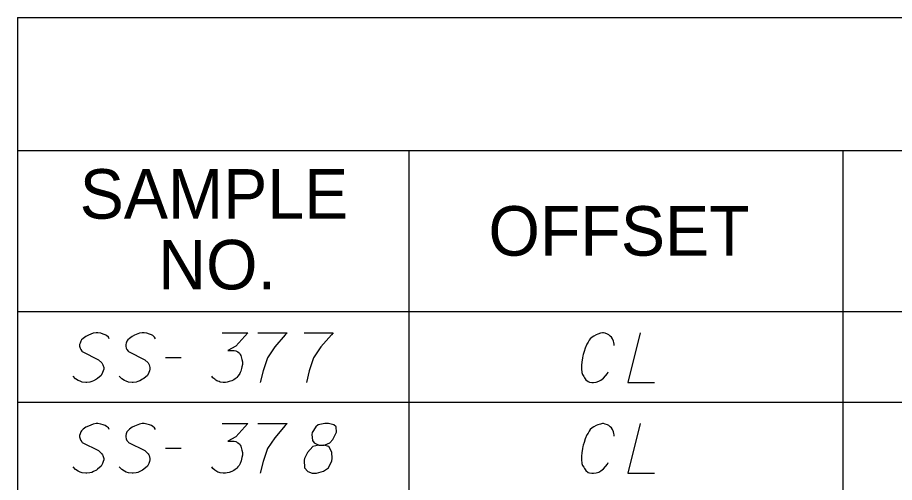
# Model space of a CAD drawing. Extents: x 2074207 to 2076812, y 516372 to 523312.
# Drawn here: x 2076260.6 to 2076345.6, y 517347 to 517392.1 of the extents above; entities that cross this region are included whole.
import ezdxf

# ---------------------------------------------------------------- set-up
doc = ezdxf.new("R2010")
doc.units = 0
for name, color, linetype in [('Prop DirtTable_ Soil Test Results - Outline (Major)', 7, 'Continuous'), ('Prop DirtTable_ Soil Test Results - Outline (Minor)', 7, 'Continuous'), ('Prop DirtTable_ Soil Test Results - Tx (Header - Small)', 7, 'Continuous'), ('Prop DirtTable_ Soil Test Results - Tx (Sample Data)', 7, 'Continuous')]:
    doc.layers.add(name, color=color, linetype=linetype)

msp = doc.modelspace()

# ---------------------------------------------------------------- linework, layer by layer
at = {"layer": 'Prop DirtTable_ Soil Test Results - Outline (Major)'}
for p, q in [((2076260.609, 517392.071), (2076260.609, 517363.585)), ((2076260.609, 517392.071), (2076811.903, 517392.071)), ((2076260.609, 517363.585), (2076260.609, 517354.785)), ((2076260.609, 517363.585), (2076811.903, 517363.585)), ((2076260.609, 517363.585), (2076811.903, 517363.585)), ((2076260.609, 517354.785), (2076260.609, 517345.985))]:
    msp.add_line(p, q, dxfattribs=at)
at = {"layer": 'Prop DirtTable_ Soil Test Results - Outline (Minor)'}
for p, q in [((2076260.609, 517379.185), (2076811.903, 517379.185)), ((2076298.545, 517379.185), (2076298.545, 517354.785)), ((2076340.594, 517379.185), (2076340.594, 517354.785)), ((2076260.609, 517354.785), (2076811.903, 517354.785)), ((2076260.609, 517354.785), (2076811.903, 517354.785)), ((2076298.546, 517354.785), (2076298.546, 517345.985)), ((2076340.594, 517354.785), (2076340.594, 517345.985))]:
    msp.add_line(p, q, dxfattribs=at)
at = {"layer": 'Prop DirtTable_ Soil Test Results - Tx (Sample Data)'}
for points in [[(2076269.488, 517360.931), (2076269.417, 517361.082), (2076269.241, 517361.233), (2076269.1, 517361.309), (2076268.923, 517361.385), (2076268.677, 517361.46), (2076268.394, 517361.498), (2076268.218, 517361.498), (2076267.936, 517361.46), (2076267.477, 517361.271), (2076267.23, 517361.158), (2076266.983, 517360.969), (2076266.807, 517360.818), (2076266.736, 517360.704), (2076266.666, 517360.515), (2076266.631, 517360.364), (2076266.631, 517360.213), (2076266.666, 517360.024), (2076266.736, 517359.873), (2076266.842, 517359.722), (2076266.878, 517359.684), (2076268.465, 517358.89), (2076268.782, 517358.588), (2076268.853, 517358.474), (2076268.888, 517358.399), (2076268.959, 517358.134), (2076268.959, 517357.983), (2076268.923, 517357.832), (2076268.853, 517357.643), (2076268.712, 517357.378), (2076268.359, 517357.076), (2076268.253, 517357), (2076267.971, 517356.849), (2076267.795, 517356.774), (2076267.618, 517356.736), (2076267.336, 517356.698), (2076267.23, 517356.698), (2076266.878, 517356.736), (2076266.666, 517356.811), (2076266.489, 517356.887), (2076266.243, 517357.038), (2076265.996, 517357.303)], [(2076273.968, 517360.931), (2076273.897, 517361.082), (2076273.721, 517361.233), (2076273.58, 517361.309), (2076273.403, 517361.385), (2076273.157, 517361.46), (2076272.874, 517361.498), (2076272.698, 517361.498), (2076272.416, 517361.46), (2076271.957, 517361.271), (2076271.71, 517361.158), (2076271.463, 517360.969), (2076271.287, 517360.818), (2076271.216, 517360.704), (2076271.146, 517360.515), (2076271.111, 517360.364), (2076271.111, 517360.213), (2076271.146, 517360.024), (2076271.216, 517359.873), (2076271.322, 517359.722), (2076271.358, 517359.684), (2076272.945, 517358.89), (2076273.262, 517358.588), (2076273.333, 517358.474), (2076273.368, 517358.399), (2076273.439, 517358.134), (2076273.439, 517357.983), (2076273.403, 517357.832), (2076273.333, 517357.643), (2076273.192, 517357.378), (2076272.839, 517357.076), (2076272.733, 517357), (2076272.451, 517356.849), (2076272.275, 517356.774), (2076272.098, 517356.736), (2076271.816, 517356.698), (2076271.71, 517356.698), (2076271.358, 517356.736), (2076271.146, 517356.811), (2076270.969, 517356.887), (2076270.723, 517357.038), (2076270.476, 517357.303)], [(2076280.459, 517361.498), (2076282.928, 517361.498), (2076281.764, 517360.213), (2076280.988, 517359.797), (2076281.623, 517359.797), (2076281.764, 517359.759), (2076281.834, 517359.722), (2076281.905, 517359.684), (2076281.975, 517359.646), (2076282.117, 517359.533), (2076282.187, 517359.419), (2076282.258, 517359.306), (2076282.293, 517359.192), (2076282.363, 517358.928), (2076282.399, 517358.701), (2076282.399, 517358.588), (2076282.399, 517358.437), (2076282.363, 517358.21), (2076282.328, 517358.059), (2076282.293, 517357.907), (2076282.258, 517357.794), (2076282.222, 517357.718), (2076282.187, 517357.643), (2076282.152, 517357.567), (2076282.081, 517357.454), (2076281.975, 517357.303), (2076281.87, 517357.189), (2076281.799, 517357.114), (2076281.693, 517357.038), (2076281.587, 517356.963), (2076281.446, 517356.887), (2076281.376, 517356.849), (2076281.129, 517356.774), (2076280.917, 517356.736), (2076280.776, 517356.698), (2076280.529, 517356.698), (2076280.247, 517356.736), (2076280.141, 517356.774), (2076280.035, 517356.811), (2076279.929, 517356.849), (2076279.824, 517356.925), (2076279.718, 517357), (2076279.541, 517357.152), (2076279.436, 517357.303)], [(2076283.916, 517361.498), (2076286.738, 517361.498), (2076286.561, 517361.309), (2076285.538, 517360.137), (2076284.833, 517359.079), (2076284.409, 517357.832), (2076284.127, 517356.698)], [(2076288.396, 517361.498), (2076291.218, 517361.498), (2076291.041, 517361.309), (2076290.018, 517360.137), (2076289.313, 517359.079), (2076288.889, 517357.832), (2076288.607, 517356.698)], [(2076318.45, 517360.289), (2076318.45, 517360.402), (2076318.415, 517360.553), (2076318.38, 517360.704), (2076318.309, 517360.855), (2076318.274, 517360.931), (2076318.168, 517361.082), (2076318.062, 517361.196), (2076317.921, 517361.309), (2076317.78, 517361.385), (2076317.569, 517361.46), (2076317.392, 517361.498), (2076317.322, 517361.498), (2076317.11, 517361.46), (2076316.863, 517361.385), (2076316.687, 517361.309), (2076316.475, 517361.196), (2076316.299, 517361.082), (2076316.122, 517360.931), (2076316.016, 517360.78), (2076315.911, 517360.591), (2076315.805, 517360.402), (2076315.628, 517360.024), (2076315.523, 517359.684), (2076315.452, 517359.419), (2076315.417, 517359.268), (2076315.381, 517359.079), (2076315.311, 517358.663), (2076315.276, 517358.361), (2076315.276, 517358.021), (2076315.311, 517357.643), (2076315.381, 517357.454), (2076315.487, 517357.265), (2076315.558, 517357.152), (2076315.699, 517356.963), (2076315.911, 517356.774), (2076316.052, 517356.736), (2076316.263, 517356.698), (2076316.404, 517356.698), (2076316.44, 517356.698), (2076316.687, 517356.736), (2076316.969, 517356.811), (2076317.145, 517356.925), (2076317.392, 517357.114), (2076317.604, 517357.341), (2076317.78, 517357.567), (2076317.851, 517357.718)], [(2076320.955, 517361.498), (2076319.756, 517356.698), (2076322.366, 517356.698)], [(2076274.956, 517359.117), (2076276.472, 517359.117)], [(2076269.488, 517352.131), (2076269.417, 517352.282), (2076269.241, 517352.433), (2076269.1, 517352.509), (2076268.923, 517352.585), (2076268.677, 517352.66), (2076268.394, 517352.698), (2076268.218, 517352.698), (2076267.936, 517352.66), (2076267.477, 517352.471), (2076267.23, 517352.358), (2076266.983, 517352.169), (2076266.807, 517352.018), (2076266.736, 517351.904), (2076266.666, 517351.715), (2076266.631, 517351.564), (2076266.631, 517351.413), (2076266.666, 517351.224), (2076266.736, 517351.073), (2076266.842, 517350.922), (2076266.878, 517350.884), (2076268.465, 517350.09), (2076268.782, 517349.788), (2076268.853, 517349.674), (2076268.888, 517349.599), (2076268.959, 517349.334), (2076268.959, 517349.183), (2076268.923, 517349.032), (2076268.853, 517348.843), (2076268.712, 517348.578), (2076268.359, 517348.276), (2076268.253, 517348.2), (2076267.971, 517348.049), (2076267.795, 517347.974), (2076267.618, 517347.936), (2076267.336, 517347.898), (2076267.23, 517347.898), (2076266.878, 517347.936), (2076266.666, 517348.011), (2076266.489, 517348.087), (2076266.243, 517348.238), (2076265.996, 517348.503)], [(2076273.968, 517352.131), (2076273.897, 517352.282), (2076273.721, 517352.433), (2076273.58, 517352.509), (2076273.403, 517352.585), (2076273.157, 517352.66), (2076272.874, 517352.698), (2076272.698, 517352.698), (2076272.416, 517352.66), (2076271.957, 517352.471), (2076271.71, 517352.358), (2076271.463, 517352.169), (2076271.287, 517352.018), (2076271.216, 517351.904), (2076271.146, 517351.715), (2076271.111, 517351.564), (2076271.111, 517351.413), (2076271.146, 517351.224), (2076271.216, 517351.073), (2076271.322, 517350.922), (2076271.358, 517350.884), (2076272.945, 517350.09), (2076273.262, 517349.788), (2076273.333, 517349.674), (2076273.368, 517349.599), (2076273.439, 517349.334), (2076273.439, 517349.183), (2076273.403, 517349.032), (2076273.333, 517348.843), (2076273.192, 517348.578), (2076272.839, 517348.276), (2076272.733, 517348.2), (2076272.451, 517348.049), (2076272.275, 517347.974), (2076272.098, 517347.936), (2076271.816, 517347.898), (2076271.71, 517347.898), (2076271.358, 517347.936), (2076271.146, 517348.011), (2076270.969, 517348.087), (2076270.723, 517348.238), (2076270.476, 517348.503)], [(2076280.459, 517352.698), (2076282.928, 517352.698), (2076281.764, 517351.413), (2076280.988, 517350.997), (2076281.623, 517350.997), (2076281.764, 517350.959), (2076281.834, 517350.922), (2076281.905, 517350.884), (2076281.975, 517350.846), (2076282.117, 517350.733), (2076282.187, 517350.619), (2076282.258, 517350.506), (2076282.293, 517350.392), (2076282.363, 517350.128), (2076282.399, 517349.901), (2076282.399, 517349.788), (2076282.399, 517349.637), (2076282.363, 517349.41), (2076282.328, 517349.259), (2076282.293, 517349.107), (2076282.258, 517348.994), (2076282.222, 517348.918), (2076282.187, 517348.843), (2076282.152, 517348.767), (2076282.081, 517348.654), (2076281.975, 517348.503), (2076281.87, 517348.389), (2076281.799, 517348.314), (2076281.693, 517348.238), (2076281.587, 517348.163), (2076281.446, 517348.087), (2076281.376, 517348.049), (2076281.129, 517347.974), (2076280.917, 517347.936), (2076280.776, 517347.898), (2076280.529, 517347.898), (2076280.247, 517347.936), (2076280.141, 517347.974), (2076280.035, 517348.011), (2076279.929, 517348.049), (2076279.824, 517348.125), (2076279.718, 517348.2), (2076279.541, 517348.352), (2076279.436, 517348.503)], [(2076283.916, 517352.698), (2076286.738, 517352.698), (2076286.561, 517352.509), (2076285.538, 517351.337), (2076284.833, 517350.279), (2076284.409, 517349.032), (2076284.127, 517347.898)], [(2076289.807, 517350.619), (2076290.3, 517350.619), (2076290.442, 517350.657), (2076290.865, 517350.846), (2076291.182, 517351.148), (2076291.535, 517351.867), (2076291.5, 517352.396), (2076291.253, 517352.585), (2076290.759, 517352.698), (2076290.406, 517352.698), (2076289.736, 517352.585), (2076289.524, 517352.396), (2076289.172, 517351.829), (2076289.136, 517351.64), (2076289.207, 517351.073), (2076289.348, 517350.846), (2076289.807, 517350.619), (2076289.242, 517350.468), (2076288.713, 517349.901), (2076288.431, 517349.334), (2076288.396, 517349.145), (2076288.431, 517348.427), (2076288.748, 517348.049), (2076289.172, 517347.898), (2076289.595, 517347.898), (2076290.265, 517348.087), (2076290.759, 517348.427), (2076291.077, 517349.107), (2076291.112, 517349.334), (2076291.077, 517349.939), (2076290.794, 517350.468), (2076290.3, 517350.619)], [(2076318.45, 517351.489), (2076318.45, 517351.602), (2076318.415, 517351.753), (2076318.38, 517351.904), (2076318.309, 517352.055), (2076318.274, 517352.131), (2076318.168, 517352.282), (2076318.062, 517352.396), (2076317.921, 517352.509), (2076317.78, 517352.585), (2076317.569, 517352.66), (2076317.392, 517352.698), (2076317.322, 517352.698), (2076317.11, 517352.66), (2076316.863, 517352.585), (2076316.687, 517352.509), (2076316.475, 517352.396), (2076316.299, 517352.282), (2076316.122, 517352.131), (2076316.016, 517351.98), (2076315.911, 517351.791), (2076315.805, 517351.602), (2076315.628, 517351.224), (2076315.523, 517350.884), (2076315.452, 517350.619), (2076315.417, 517350.468), (2076315.381, 517350.279), (2076315.311, 517349.863), (2076315.276, 517349.561), (2076315.276, 517349.221), (2076315.311, 517348.843), (2076315.381, 517348.654), (2076315.487, 517348.465), (2076315.558, 517348.352), (2076315.699, 517348.163), (2076315.911, 517347.974), (2076316.052, 517347.936), (2076316.263, 517347.898), (2076316.404, 517347.898), (2076316.44, 517347.898), (2076316.687, 517347.936), (2076316.969, 517348.011), (2076317.145, 517348.125), (2076317.392, 517348.314), (2076317.604, 517348.541), (2076317.78, 517348.767), (2076317.851, 517348.918)], [(2076320.955, 517352.698), (2076319.756, 517347.898), (2076322.366, 517347.898)], [(2076274.956, 517350.317), (2076276.472, 517350.317)]]:
    msp.add_lwpolyline(points, dxfattribs=at)

# ---------------------------------------------------------------- texts
at = {"layer": 'Prop DirtTable_ Soil Test Results - Tx (Header - Small)'}
for s, p in [('SAMPLE', (2076266.632, 517372.572)), ('OFFSET', (2076306.254, 517368.986)), ('NO.', (2076274.244, 517365.715))]:
    msp.add_text(s, height=4.8, dxfattribs=at).set_placement(p)

doc.saveas('drawing.dxf')
